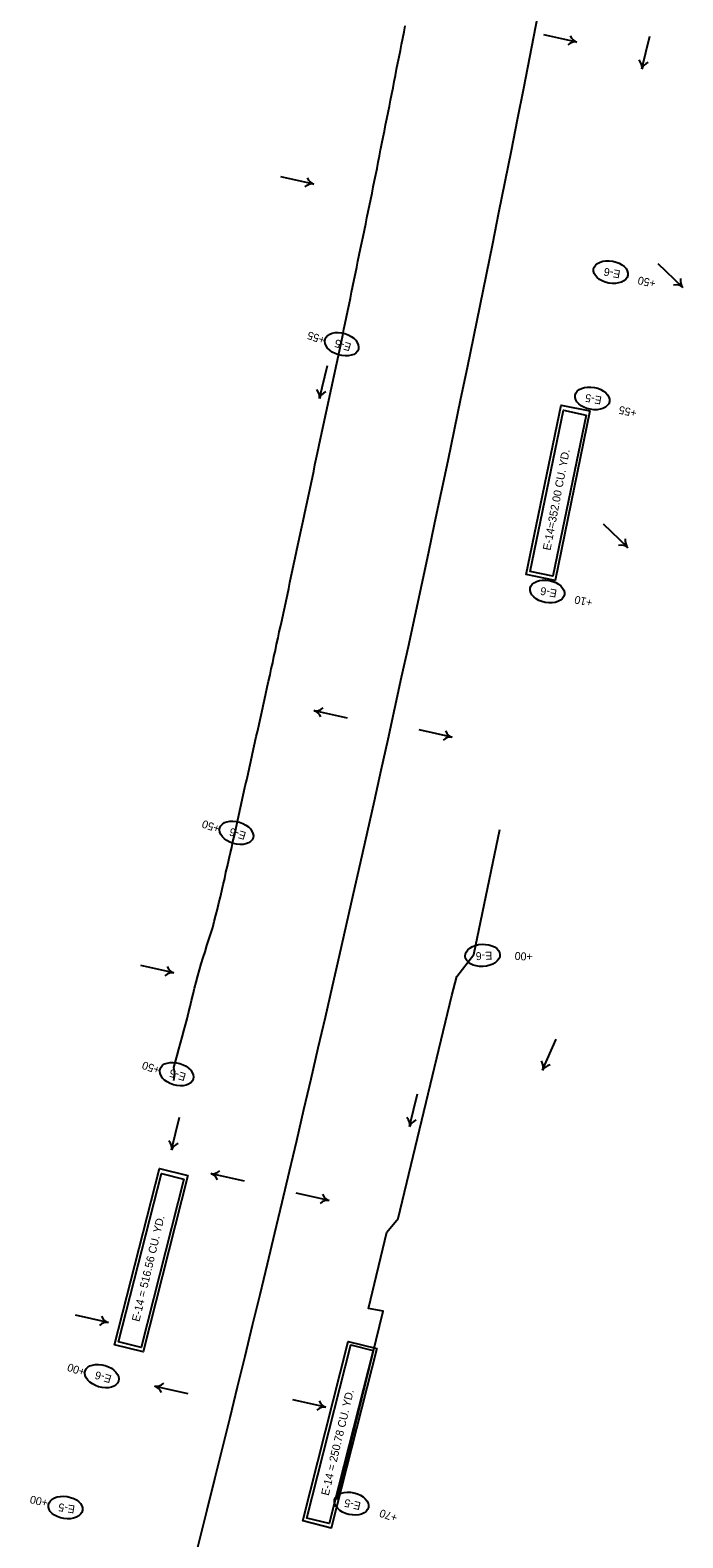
# Model space of a CAD drawing. Extents: x 669236 to 673912, y 735758 to 754788.
# Drawn here: x 670064 to 670579, y 739545 to 740733 of the extents above; entities that cross this region are included whole.
import ezdxf

# ---------------------------------------------------------------- set-up
doc = ezdxf.new("R2010")
doc.units = 0
for name, color, linetype in [('Default', 7, 'Continuous'), ('R_Ditchline', 7, 'Continuous'), ('R_Erosion_3', 7, 'Continuous'), ('R_Flow Arrows', 7, 'Continuous')]:
    doc.layers.add(name, color=color, linetype=linetype)

msp = doc.modelspace()

# ---------------------------------------------------------------- linework, layer by layer
at = {"layer": 'Default'}
msp.add_arc((647964.6, 745104.3), 22918.3, 345.76855, 349.76105, dxfattribs=at)
at = {"layer": 'R_Ditchline'}
msp.add_lwpolyline([(670177.5, 739905.1), (670178.3, 739910), (670178.4, 739910.6), (670177.5, 739915.3), (670178.8, 739920.1), (670180.1, 739924.9), (670181.4, 739929.8), (670182.7, 739934.6), (670184, 739939.4), (670185.3, 739944.2), (670186.6, 739949), (670187.9, 739953.8), (670189.1, 739958.6), (670190.3, 739963.5), (670191.5, 739968.3), (670192.7, 739973.1), (670193.9, 739977.9), (670195.1, 739982.8), (670196.4, 739987.6), (670197.6, 739992.4), (670199, 739997.2), (670200.5, 740002), (670202.1, 740006.7), (670203.6, 740011.5), (670205.1, 740016.2), (670206.7, 740021), (670208.2, 740025.7), (670209.4, 740030.6), (670210.6, 740035.4), (670211.8, 740040.2), (670213, 740045.1), (670214.2, 740049.9), (670215.3, 740054.7), (670216.4, 740059.6), (670217.6, 740064.4), (670218.6, 740069.3), (670219.7, 740074.2), (670220.8, 740079), (670221.9, 740083.9), (670223.1, 740088.7), (670224.1, 740093.6), (670225.2, 740098.4), (670226.3, 740103.3), (670227.4, 740108.2), (670228.5, 740113), (670229.5, 740117.9), (670230.6, 740122.7), (670231.7, 740127.6), (670232.7, 740132.5), (670233.8, 740137.3), (670234.9, 740142.2), (670236, 740147), (670237.1, 740151.9), (670238.2, 740156.7), (670239.2, 740161.6), (670240.3, 740166.5), (670241.4, 740171.3), (670242.5, 740176.2), (670243.6, 740181), (670244.7, 740185.9), (670245.8, 740190.8), (670246.9, 740195.6), (670247.9, 740200.5), (670249, 740205.3), (670250.1, 740210.2), (670251.1, 740215.1), (670252.2, 740219.9), (670253.3, 740224.8), (670254.3, 740229.6), (670255.4, 740234.5), (670256.4, 740239.4), (670257.5, 740244.2), (670258.5, 740249.1), (670259.6, 740254), (670260.6, 740258.8), (670261.7, 740263.7), (670262.8, 740268.6), (670263.8, 740273.4), (670264.9, 740278.3), (670265.9, 740283.2), (670267, 740288), (670268, 740292.9), (670269, 740297.8), (670270, 740302.6), (670271.1, 740307.5), (670272.1, 740312.4), (670273.2, 740317.2), (670274.2, 740322.1), (670275.3, 740327), (670276.3, 740331.8), (670277.3, 740336.7), (670278.4, 740341.6), (670279.5, 740346.4), (670280.5, 740351.3), (670281.6, 740356.2), (670282.6, 740361), (670283.6, 740365.9), (670284.6, 740370.8), (670285.7, 740375.7), (670286.7, 740380.5), (670287.7, 740385.4), (670288.7, 740390.3), (670289.7, 740395.1), (670290.8, 740400), (670291.8, 740404.9), (670292.8, 740409.8), (670293.8, 740414.6), (670294.9, 740419.5), (670295.9, 740424.4), (670297, 740429.2), (670298.1, 740434.1), (670299.2, 740438.9), (670300.2, 740443.8), (670301.2, 740448.7), (670302.3, 740453.5), (670303.3, 740458.4), (670304.4, 740463.3), (670305.5, 740468.1), (670306.6, 740473), (670307.6, 740477.9), (670308.6, 740482.7), (670309.7, 740487.6), (670310.6, 740492.5), (670311.6, 740497.4), (670312.6, 740502.2), (670313.7, 740507.1), (670314.7, 740512), (670315.7, 740516.9), (670316.6, 740521.7), (670317.6, 740526.6), (670318.6, 740531.5), (670319.6, 740536.4), (670320.6, 740541.3), (670321.6, 740546.1), (670322.6, 740551), (670323.6, 740555.9), (670324.6, 740560.8), (670325.6, 740565.6), (670326.6, 740570.5), (670327.7, 740575.4), (670328.7, 740580.3), (670329.7, 740585.1), (670330.7, 740590), (670331.7, 740594.9), (670332.7, 740599.7), (670333.7, 740604.6), (670334.7, 740609.5), (670335.7, 740614.4), (670336.7, 740619.3), (670337.7, 740624.1), (670338.6, 740629), (670339.6, 740633.9), (670340.5, 740638.8), (670340.7, 740639.7), (670341.5, 740643.7), (670342.5, 740648.6), (670343.5, 740653.4), (670344.4, 740658.3), (670345.4, 740663.2), (670346.4, 740668.1), (670347.4, 740673), (670348.3, 740677.9), (670349.3, 740682.7), (670350.3, 740687.6), (670351.2, 740692.5), (670352.2, 740697.4), (670353.1, 740702.3), (670354.1, 740707.2), (670355.1, 740712), (670356, 740716.9), (670357, 740721.8), (670358, 740726.7), (670358.9, 740731.6), (670359.9, 740736.5)], dxfattribs=at)
at = {"layer": 'R_Erosion_3'}
for points in [[(670505.4, 740432.9), (670477.9, 740299.2), (670455.2, 740303.9), (670482.7, 740437.5)], [(670502.4, 740429.7), (670476.2, 740302.6), (670458.3, 740306.3), (670484.5, 740433.4)], [(670188.5, 739830.2), (670153.2, 739691.2), (670130.8, 739696.9), (670166.1, 739835.9)], [(670185.4, 739827.5), (670151.7, 739694.7), (670134, 739699.2), (670167.8, 739832)], [(670337.4, 739693.9), (670301.5, 739552.4), (670279.1, 739558.1), (670315, 739699.6)], [(670334.7, 739692.4), (670300, 739555.9), (670282.3, 739560.3), (670317, 739696.9)]]:
    msp.add_lwpolyline(points, close=True, dxfattribs=at)
msp.add_lwpolyline([(670306.2, 739574.9), (670342.4, 739723.5), (670331, 739725.6), (670345.3, 739785.6), (670354.3, 739796.5), (670396.6, 739972.2), (670400.4, 739987.2), (670414, 740004.6), (670434.5, 740103.1)], dxfattribs=at)
for centre, major_axis in [((670521.8, 740542.3), (-13.5, 2.5)), ((670309.8, 740485.5), (-13.1, 4)), ((670507.3, 740442.8), (-13.5, 2.5)), ((670471.8, 740290.6), (-13.5, 2.5)), ((670226.8, 740100.4), (-13.1, 4)), ((670420.8, 740003.8), (-13.7, -0.6)), ((670179.7, 739910.2), (-13.1, 4)), ((670120.8, 739672.2), (-13.1, 4)), ((670092.1, 739568.6), (-13.5, 2.1)), ((670317.5, 739571.7), (-13.3, 3.1))]:
    msp.add_ellipse(centre, major_axis=major_axis, ratio=0.638788, dxfattribs=at)
at = {"layer": 'R_Flow Arrows'}
for p, q in [((670495, 740723.6), (670469, 740729.4)), ((670546.3, 740702.5), (670552.6, 740728.3)), ((670287.7, 740611.7), (670261.8, 740617.5)), ((670578.5, 740530.4), (670559.3, 740548.8)), ((670292.2, 740442.8), (670298.5, 740468.6)), ((670535.2, 740325.3), (670516, 740343.6)), ((670288.1, 740196.7), (670314, 740190.9)), ((670396.7, 740175.8), (670370.8, 740181.5)), ((670177.4, 739990), (670151.5, 739995.8)), ((670468.1, 739913.4), (670478.8, 739937.7)), ((670363.3, 739868.9), (670369.6, 739894.7)), ((670175.7, 739850.5), (670182, 739876.3)), ((670206.8, 739831.8), (670232.8, 739826)), ((670299.8, 739810.6), (670273.8, 739816.4)), ((670125.8, 739714.4), (670099.9, 739720.2)), ((670162.5, 739664.2), (670188.5, 739658.5)), ((670297.2, 739647.7), (670271.3, 739653.5))]:
    msp.add_line(p, q, dxfattribs=at)
for centre, major_axis, start_param, end_param in [((670499.8, 740743.2), (-4.4, -19.7), 5.662936, 6.259934), ((670490.8, 740703.9), (4.4, 19.7), 0.023252, 0.620249), ((670526.7, 740707), (19.6, -4.8), 0.023252, 0.620249), ((670565.8, 740697.3), (-19.6, 4.8), 5.662936, 6.259934), ((670283.6, 740592), (4.4, 19.7), 0.023252, 0.620249), ((670292.5, 740631.3), (-4.4, -19.7), 5.662936, 6.259934), ((670592.8, 740544.7), (-13.9, -14.6), 5.662936, 6.259934), ((670564.8, 740515.7), (13.9, 14.6), 0.023252, 0.620249), ((670272.6, 740447.3), (19.6, -4.8), 0.023252, 0.620249), ((670311.7, 740437.6), (-19.6, 4.8), 5.662936, 6.259934), ((670521.5, 740310.5), (13.9, 14.6), 0.023252, 0.620249), ((670549.4, 740339.5), (-13.9, -14.6), 5.662936, 6.259934), ((670283.3, 740177.1), (4.4, 19.7), 5.662936, 6.259934), ((670292.2, 740216.4), (-4.4, -19.7), 0.023252, 0.620249), ((670401.5, 740195.3), (-4.4, -19.7), 5.662936, 6.259934), ((670392.6, 740156), (4.4, 19.7), 0.023252, 0.620249), ((670173.3, 739970.3), (4.4, 19.7), 0.023252, 0.620249), ((670182.2, 740009.6), (-4.4, -19.7), 5.662936, 6.259934), ((670449.6, 739921.2), (18.5, -8.1), 0.023252, 0.620249), ((670486.4, 739904.8), (-18.5, 8.1), 5.662936, 6.259934), ((670343.7, 739873.4), (19.6, -4.8), 0.023252, 0.620249), ((670382.8, 739863.7), (-19.6, 4.8), 5.662936, 6.259934), ((670156.1, 739855), (19.6, -4.8), 0.023252, 0.620249), ((670195.2, 739845.3), (-19.6, 4.8), 5.662936, 6.259934), ((670202, 739812.2), (4.4, 19.7), 5.662936, 6.259934), ((670211, 739851.5), (-4.4, -19.7), 0.023252, 0.620249), ((670295.6, 739790.9), (4.4, 19.7), 0.023252, 0.620249), ((670304.6, 739830.2), (-4.4, -19.7), 5.662936, 6.259934), ((670130.6, 739734), (-4.4, -19.7), 5.662936, 6.259934), ((670121.7, 739694.7), (4.4, 19.7), 0.023252, 0.620249), ((670157.7, 739644.6), (4.4, 19.7), 5.662936, 6.259934), ((670166.7, 739684), (-4.4, -19.7), 0.023252, 0.620249), ((670293.1, 739628), (4.4, 19.7), 0.023252, 0.620249), ((670302, 739667.3), (-4.4, -19.7), 5.662936, 6.259934)]:
    msp.add_ellipse(centre, major_axis=major_axis, ratio=0.5625, start_param=start_param, end_param=end_param, dxfattribs=at)

# ---------------------------------------------------------------- texts
at = {"layer": 'R_Erosion_3'}
for s, rotation, p in [('E-6', 169.6427, (670529.8, 740543.5)), ('+50', 167.5318, (670557.8, 740536)), ('+55', 161.0258, (670297.4, 740491.2)), ('E-5', 163.1367, (670317.8, 740485.8)), ('E-5', 169.6427, (670515.1, 740444.1)), ('+55', 167.5318, (670542.8, 740433.9)), ('E-14=352.00 CU. YD.', 79.1185, (670474.3, 740322.6)), ('E-6', 169.6427, (670479.8, 740291.9)), ('+10', 167.5318, (670507.9, 740284.4)), ('+50', 161.0258, (670214.4, 740106.1)), ('E-6', 163.1367, (670234.9, 740100.7)), ('E-6', 182.4753, (670428.3, 740006.8)), ('+00', 176.5027, (670460.5, 740005.7)), ('+50', 161.0258, (670167.2, 739915.9)), ('E-5', 163.1367, (670187.6, 739910.6)), ('E-14 = 516.56 CU. YD.', 76.5006, (670150.3, 739714.7)), ('+00', 161.0258, (670108.3, 739677.9)), ('E-6', 163.1367, (670128.9, 739672.5)), ('E-14 = 250.78 CU. YD.', 76.5006, (670299.5, 739577.6)), ('+00', 166.603, (670078.8, 739575)), ('E-5', 166.9984, (670325.3, 739572.6)), ('E-5', 171.2314, (670099.9, 739570.1)), ('+70', 161.0258, (670354.3, 739562.9))]:
    msp.add_text(s, height=6.25, rotation=rotation, dxfattribs=at).set_placement(p)

doc.saveas('drawing.dxf')
